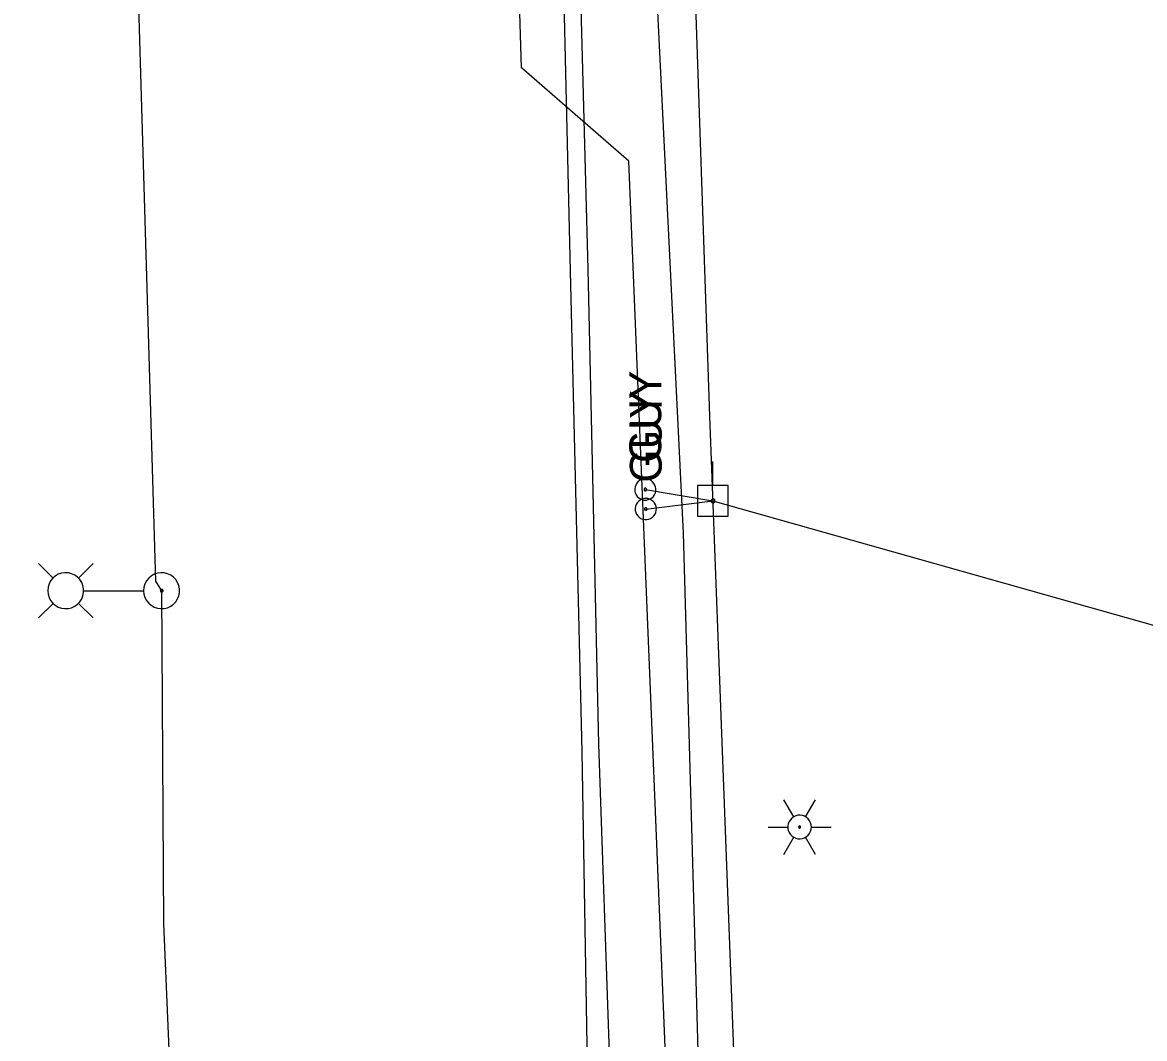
# Model space of a CAD drawing. Extents: x 596028 to 606371, y 330010 to 403088.
# Drawn here: x 604931 to 605066.7, y 335039.8 to 335162.8 of the extents above; entities that cross this region are included whole.
import ezdxf

# ---------------------------------------------------------------- set-up
doc = ezdxf.new("R2010")
doc.units = 0
for name, color, linetype in [('E_LTG', 7, 'Continuous'), ('E_LTG_CID', 7, 'Continuous'), ('E_UTL_EGuyWire', 7, 'Continuous'), ('E_UTL_EPowerPole', 7, 'Continuous'), ('E_UTL_G_UG', 7, 'Continuous'), ('E_UTL_Overhead', 7, 'Continuous'), ('E_UTL_W_UG', 7, 'Continuous')]:
    doc.layers.add(name, color=color, linetype=linetype)

msp = doc.modelspace()

# ---------------------------------------------------------------- linework, layer by layer
at = {"layer": 'E_LTG'}
for points in [[(604934.7, 335095.52), (604932.93, 335097.3)], [(604934.05, 335094), (604934.09, 335093.59), (604934.21, 335093.19), (604934.4, 335092.82), (604934.65, 335092.5), (604934.96, 335092.23), (604935.32, 335092.02), (604935.71, 335091.89), (604936.12, 335091.83), (604936.54, 335091.85), (604936.94, 335091.94), (604937.31, 335092.12), (604937.65, 335092.36), (604937.94, 335092.65), (604938.16, 335093), (604938.31, 335093.39), (604938.39, 335093.79), (604938.39, 335094.21), (604938.31, 335094.61), (604938.16, 335095), (604937.94, 335095.34), (604937.65, 335095.64), (604937.31, 335095.88), (604936.94, 335096.06), (604936.54, 335096.15), (604936.12, 335096.17), (604935.71, 335096.11), (604935.32, 335095.98), (604934.96, 335095.77), (604934.65, 335095.5), (604934.4, 335095.18), (604934.21, 335094.81), (604934.09, 335094.41), (604934.05, 335094)], [(604937.75, 335095.52), (604939.53, 335097.3)], [(604945.65, 335094), (604945.69, 335093.59), (604945.81, 335093.19), (604946, 335092.82), (604946.26, 335092.5), (604946.57, 335092.23), (604946.93, 335092.02), (604947.32, 335091.89), (604947.73, 335091.83), (604948.14, 335091.85), (604948.54, 335091.94), (604948.92, 335092.12), (604949.25, 335092.36), (604949.54, 335092.65), (604949.76, 335093), (604949.92, 335093.39), (604950, 335093.79), (604950, 335094.21), (604949.92, 335094.61), (604949.76, 335095), (604949.54, 335095.34), (604949.25, 335095.64), (604948.92, 335095.88), (604948.54, 335096.06), (604948.14, 335096.15), (604947.73, 335096.17), (604947.32, 335096.11), (604946.93, 335095.98), (604946.57, 335095.77), (604946.26, 335095.5), (604946, 335095.18), (604945.81, 335094.81), (604945.69, 335094.41), (604945.65, 335094)], [(604938.44, 335094), (604945.62, 335094)], [(604947.66, 335094), (604947.67, 335093.97), (604947.68, 335093.94), (604947.69, 335093.91), (604947.71, 335093.88), (604947.73, 335093.86), (604947.76, 335093.85), (604947.79, 335093.84), (604947.82, 335093.83), (604947.85, 335093.84), (604947.88, 335093.84), (604947.91, 335093.86), (604947.94, 335093.87), (604947.96, 335093.9), (604947.98, 335093.92), (604947.99, 335093.95), (604948, 335093.98), (604948, 335094.02), (604947.99, 335094.05), (604947.98, 335094.08), (604947.96, 335094.1), (604947.94, 335094.13), (604947.91, 335094.14), (604947.88, 335094.16), (604947.85, 335094.16), (604947.82, 335094.17), (604947.79, 335094.16), (604947.76, 335094.15), (604947.73, 335094.14), (604947.71, 335094.11), (604947.69, 335094.09), (604947.68, 335094.06), (604947.67, 335094.03), (604947.66, 335094)], [(604934.7, 335092.47), (604932.93, 335090.7)], [(604937.75, 335092.47), (604939.53, 335090.7)], [(605024.27, 335066.64), (605023.08, 335068.7)], [(605025.7, 335066.64), (605026.89, 335068.7)], [(605026.41, 335065.4), (605026.39, 335065.67), (605026.31, 335065.93), (605026.18, 335066.17), (605026.02, 335066.39), (605025.81, 335066.57), (605025.58, 335066.7), (605025.32, 335066.79), (605025.05, 335066.83), (605024.78, 335066.82), (605024.51, 335066.75), (605024.27, 335066.64), (605024.05, 335066.48), (605023.86, 335066.29), (605023.71, 335066.06), (605023.61, 335065.8), (605023.56, 335065.54), (605023.56, 335065.27), (605023.61, 335065), (605023.71, 335064.75), (605023.86, 335064.52), (605024.05, 335064.32), (605024.27, 335064.16), (605024.51, 335064.05), (605024.78, 335063.99), (605025.05, 335063.97), (605025.32, 335064.01), (605025.58, 335064.1), (605025.81, 335064.24), (605026.02, 335064.42), (605026.18, 335064.63), (605026.31, 335064.87), (605026.39, 335065.13), (605026.41, 335065.4)], [(605026.41, 335065.4), (605026.39, 335065.67), (605026.31, 335065.93), (605026.18, 335066.17), (605026.02, 335066.39), (605025.81, 335066.57), (605025.58, 335066.7), (605025.32, 335066.79), (605025.05, 335066.83), (605024.78, 335066.82), (605024.51, 335066.75), (605024.27, 335066.64), (605024.05, 335066.48), (605023.86, 335066.29), (605023.71, 335066.06), (605023.61, 335065.8), (605023.56, 335065.54), (605023.56, 335065.27), (605023.61, 335065), (605023.71, 335064.75), (605023.86, 335064.52), (605024.05, 335064.32), (605024.27, 335064.16), (605024.51, 335064.05), (605024.78, 335063.99), (605025.05, 335063.97), (605025.32, 335064.01), (605025.58, 335064.1), (605025.81, 335064.24), (605026.02, 335064.42), (605026.18, 335064.63), (605026.31, 335064.87), (605026.39, 335065.13), (605026.41, 335065.4)], [(605026.41, 335065.4), (605026.39, 335065.67), (605026.31, 335065.93), (605026.18, 335066.17), (605026.02, 335066.39), (605025.81, 335066.57), (605025.58, 335066.7), (605025.32, 335066.79), (605025.05, 335066.83), (605024.78, 335066.82), (605024.51, 335066.75), (605024.27, 335066.64), (605024.05, 335066.48), (605023.86, 335066.29), (605023.71, 335066.06), (605023.61, 335065.8), (605023.56, 335065.54), (605023.56, 335065.27), (605023.61, 335065), (605023.71, 335064.75), (605023.86, 335064.52), (605024.05, 335064.32), (605024.27, 335064.16), (605024.51, 335064.05), (605024.78, 335063.99), (605025.05, 335063.97), (605025.32, 335064.01), (605025.58, 335064.1), (605025.81, 335064.24), (605026.02, 335064.42), (605026.18, 335064.63), (605026.31, 335064.87), (605026.39, 335065.13), (605026.41, 335065.4)], [(605021.17, 335065.4), (605023.55, 335065.4)], [(605025.1, 335065.4), (605025.1, 335065.42), (605025.09, 335065.45), (605025.08, 335065.47), (605025.07, 335065.48), (605025.05, 335065.5), (605025.03, 335065.51), (605025.01, 335065.52), (605024.99, 335065.52), (605024.97, 335065.52), (605024.94, 335065.51), (605024.92, 335065.51), (605024.9, 335065.49), (605024.89, 335065.48), (605024.88, 335065.46), (605024.87, 335065.44), (605024.86, 335065.41), (605024.86, 335065.39), (605024.87, 335065.37), (605024.88, 335065.35), (605024.89, 335065.33), (605024.9, 335065.31), (605024.92, 335065.3), (605024.94, 335065.29), (605024.97, 335065.28), (605024.99, 335065.28), (605025.01, 335065.29), (605025.03, 335065.29), (605025.05, 335065.3), (605025.07, 335065.32), (605025.08, 335065.34), (605025.09, 335065.36), (605025.1, 335065.38), (605025.1, 335065.4)], [(605026.41, 335065.4), (605028.79, 335065.4)], [(605023.08, 335062.1), (605024.27, 335064.16)], [(605026.89, 335062.1), (605025.7, 335064.16)]]:
    msp.add_lwpolyline(points, dxfattribs=at)
at = {"layer": 'E_LTG_CID'}
msp.add_lwpolyline([(604967.03, 334670.29), (604963.28, 334734.35), (604962.55, 334735.4), (604960.49, 334790.4), (604957.1, 334864.55), (604955.09, 334914.72), (604953.95, 334915.4), (604951.63, 334970.04), (604948.08, 335053.71), (604947.83, 335094), (604947.12, 335095.14), (604944.98, 335167.5), (604943.36, 335208.16), (604941.38, 335274.53), (604940.11, 335275.5), (604940.27, 335304.13), (604937.49, 335351.94), (604930.99, 335433.63)], dxfattribs=at)
at = {"layer": 'E_UTL_EGuyWire'}
for p in [(605006.32, 335106.25), (605006.37, 335103.88)]:
    msp.add_line(p, (605014.5, 335104.86), dxfattribs=at)
for points in [[(605006.32, 335107.53), (605006.07, 335107.51), (605005.84, 335107.44), (605005.62, 335107.33), (605005.43, 335107.18), (605005.27, 335106.99), (605005.15, 335106.78), (605005.07, 335106.55), (605005.03, 335106.31), (605005.05, 335106.07), (605005.1, 335105.83), (605005.2, 335105.61), (605005.35, 335105.41), (605005.52, 335105.24), (605005.73, 335105.11), (605005.95, 335105.02), (605006.19, 335104.97), (605006.44, 335104.97), (605006.68, 335105.02), (605006.9, 335105.11), (605007.11, 335105.24), (605007.29, 335105.41), (605007.43, 335105.61), (605007.53, 335105.83), (605007.59, 335106.07), (605007.6, 335106.31), (605007.56, 335106.55), (605007.48, 335106.78), (605007.36, 335106.99), (605007.2, 335107.18), (605007.01, 335107.33), (605006.79, 335107.44), (605006.56, 335107.51), (605006.32, 335107.53)], [(605006.32, 335106.41), (605006.29, 335106.41), (605006.26, 335106.4), (605006.23, 335106.38), (605006.21, 335106.37), (605006.19, 335106.34), (605006.17, 335106.32), (605006.16, 335106.29), (605006.16, 335106.26), (605006.16, 335106.23), (605006.16, 335106.2), (605006.18, 335106.17), (605006.19, 335106.14), (605006.22, 335106.12), (605006.24, 335106.11), (605006.27, 335106.1), (605006.3, 335106.09), (605006.33, 335106.09), (605006.36, 335106.1), (605006.39, 335106.11), (605006.42, 335106.12), (605006.44, 335106.14), (605006.45, 335106.17), (605006.47, 335106.2), (605006.47, 335106.23), (605006.48, 335106.26), (605006.47, 335106.29), (605006.46, 335106.32), (605006.45, 335106.34), (605006.43, 335106.37), (605006.4, 335106.38), (605006.38, 335106.4), (605006.35, 335106.41), (605006.32, 335106.41)], [(605006.37, 335105.17), (605006.13, 335105.14), (605005.9, 335105.08), (605005.68, 335104.96), (605005.49, 335104.81), (605005.33, 335104.63), (605005.21, 335104.42), (605005.13, 335104.19), (605005.09, 335103.95), (605005.1, 335103.7), (605005.16, 335103.46), (605005.26, 335103.24), (605005.4, 335103.04), (605005.58, 335102.88), (605005.79, 335102.74), (605006.01, 335102.65), (605006.25, 335102.61), (605006.5, 335102.61), (605006.74, 335102.65), (605006.96, 335102.74), (605007.17, 335102.88), (605007.34, 335103.04), (605007.49, 335103.24), (605007.59, 335103.46), (605007.64, 335103.7), (605007.66, 335103.95), (605007.62, 335104.19), (605007.54, 335104.42), (605007.42, 335104.63), (605007.26, 335104.81), (605007.07, 335104.96), (605006.85, 335105.08), (605006.62, 335105.14), (605006.37, 335105.17)], [(605006.37, 335104.04), (605006.34, 335104.04), (605006.31, 335104.03), (605006.29, 335104.02), (605006.26, 335104), (605006.24, 335103.98), (605006.23, 335103.95), (605006.22, 335103.92), (605006.21, 335103.89), (605006.22, 335103.86), (605006.22, 335103.83), (605006.24, 335103.8), (605006.25, 335103.78), (605006.27, 335103.76), (605006.3, 335103.74), (605006.33, 335103.73), (605006.36, 335103.72), (605006.39, 335103.72), (605006.42, 335103.73), (605006.45, 335103.74), (605006.47, 335103.76), (605006.5, 335103.78), (605006.51, 335103.8), (605006.53, 335103.83), (605006.53, 335103.86), (605006.53, 335103.89), (605006.53, 335103.92), (605006.52, 335103.95), (605006.5, 335103.98), (605006.48, 335104), (605006.46, 335104.02), (605006.43, 335104.03), (605006.4, 335104.04), (605006.37, 335104.04)]]:
    msp.add_lwpolyline(points, dxfattribs=at)
at = {"layer": 'E_UTL_EPowerPole'}
for points in [[(605014.47, 335106.71), (605014.47, 335109.62)], [(605016.32, 335106.71), (605012.63, 335106.71)], [(605012.63, 335106.71), (605012.63, 335103.02)], [(605016.32, 335103.02), (605016.32, 335106.71)], [(605014.74, 335104.86), (605014.74, 335104.91), (605014.73, 335104.95), (605014.71, 335104.99), (605014.68, 335105.03), (605014.64, 335105.06), (605014.6, 335105.08), (605014.56, 335105.1), (605014.52, 335105.1), (605014.47, 335105.1), (605014.43, 335105.09), (605014.39, 335105.07), (605014.35, 335105.05), (605014.32, 335105.01), (605014.29, 335104.97), (605014.28, 335104.93), (605014.27, 335104.89), (605014.27, 335104.84), (605014.28, 335104.8), (605014.29, 335104.76), (605014.32, 335104.72), (605014.35, 335104.68), (605014.39, 335104.66), (605014.43, 335104.64), (605014.47, 335104.63), (605014.52, 335104.63), (605014.56, 335104.63), (605014.6, 335104.65), (605014.64, 335104.67), (605014.68, 335104.7), (605014.71, 335104.74), (605014.73, 335104.78), (605014.74, 335104.82), (605014.74, 335104.86)], [(605012.63, 335103.02), (605016.32, 335103.02)]]:
    msp.add_lwpolyline(points, dxfattribs=at)
at = {"layer": 'E_UTL_G_UG'}
for points in [[(605023.72, 334666.34), (605022.29, 334739.51), (605020.22, 334807.28), (605015.57, 334937.18), (605010.93, 335100.97), (604997.24, 335379.56)], [(605016.63, 334727.49), (605015.37, 334743.6), (605012.34, 334785.87), (605011.57, 334815.96), (605010.04, 334859.35), (605006.31, 334924.5), (605005.36, 334959.77), (605002.04, 335036.89), (605000.68, 335075.43), (604999.39, 335132.92), (604997.4, 335208.34), (604995.8, 335285.97), (604994.4, 335323.96), (604992.67, 335364.38), (604992.54, 335374.29)], [(605013.33, 334743.69), (605010.27, 334787.12), (605009.3, 334815.19), (605006.56, 334858.9), (605003.76, 334923.65), (605002.11, 334959.03), (604999.34, 335036.59), (604998.7, 335074.56), (604997.28, 335132.65), (604995.51, 335208.22), (604992.75, 335285.26), (604992.4, 335323.58), (604991.62, 335330.84), (604990.77, 335354.04), (604990.22, 335373.94)], [(605013.33, 334743.69), (605010.27, 334787.12), (605009.3, 334815.19), (605006.56, 334858.9), (605003.76, 334923.65), (605002.11, 334959.03), (604999.34, 335036.59), (604998.7, 335074.56), (604997.28, 335132.65), (604995.51, 335208.22), (604992.75, 335285.26), (604992.4, 335323.58), (604991.62, 335330.84), (604990.77, 335354.04), (604990.22, 335373.94)]]:
    msp.add_lwpolyline(points, dxfattribs=at)
at = {"layer": 'E_UTL_Overhead'}
msp.add_line((605014.5, 335104.86), (605076.84, 335087.26), dxfattribs=at)
msp.add_lwpolyline([(605060.82, 334038.02), (605055.03, 334170.54), (605046.79, 334308.95), (605039.96, 334446.59), (605033.68, 334567.58), (605029.55, 334681.31), (605027.59, 334747.04), (605025.74, 334817.42), (605020.39, 334948.8), (605014.12, 335115.1), (605007.91, 335297.38), (604985.32, 335465.29), (604968.51, 335602.26), (604952.43, 335708.38), (604942.9, 335774.97)], dxfattribs=at)
at = {"layer": 'E_UTL_W_UG'}
msp.add_lwpolyline([(605018.55, 334724.79), (605011.47, 334971.85), (605004.33, 335145.97), (604991.33, 335157.25), (604987.53, 335283.49)], dxfattribs=at)

# ---------------------------------------------------------------- texts
at = {"layer": 'E_UTL_EGuyWire'}
for p in [(605008.24, 335109.46), (605008.3, 335107.09)]:
    msp.add_text('GUY', height=3.85, rotation=90, dxfattribs=at).set_placement(p)

doc.saveas('drawing.dxf')
